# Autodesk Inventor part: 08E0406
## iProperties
Shininess: 69.0
Length Units: 11269
Angle Units: 11279
Time Units: 11290
Mass Units: 11284
Length Display Precision: 3
Angle Display Precision: 2
Compacted: True
Company: Pneumax S.p.A.
Part Number: 08E0406
Material: Default
Description: MAGGIORAZIONE Ø4 - Ø6
Document SubType Name: Modellazione
Catalog Web Link: www.pneumaxspa.com
Density: 1.59
Volumn: 0.8648857994912436
Area: 17.092995283760587
PropertySet Name: Model Information
Control State: 0
Master: False
Checked Out: False
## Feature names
1. Revolution6
2. Foro6 [Hole]
3. Chamfer10
